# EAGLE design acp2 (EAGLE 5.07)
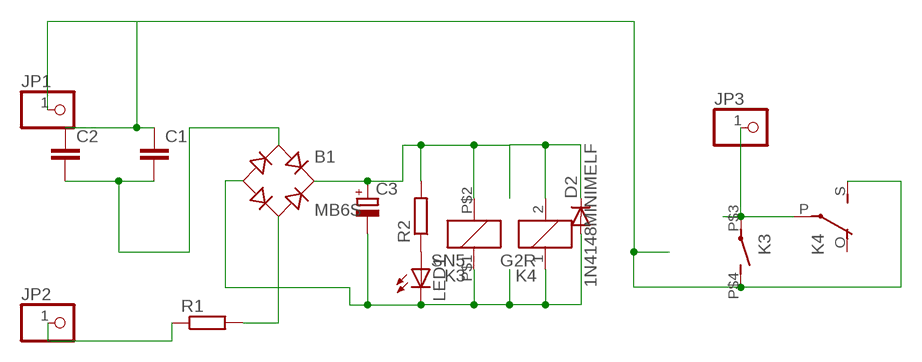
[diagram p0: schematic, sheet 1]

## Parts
B1  MB6S  [SOIC-4]
C1  C-EU150-054X183  [C150-054X183]
C2  C-EU150-054X183  [C150-054X183]
C3  CPOL-EUE2.5-5  [E2,5-5]
D2  1N4148MINIMELF  [MINIMELF]
JP1  PINHD-1X11MM6  [1X1MM8]
JP2  PINHD-1X11MM6  [1X1MM8]
JP3  PINHD-1X11MM6  [1X1MM8]
K3  SN5  [HU]
K4  G2R  [G2R]
LED1  LEDSMT1206  [1206]
R1  R-EU_0204/5  [0204/5]
R2  R-EU_R0805  [R0805]

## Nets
AC1: C1.1 C2.1 JP1.1 K3.P$4(2:S) K4.S(2:S)
AC2: JP2.1 R1.1
ACOUT: JP3.1 K3.P$3(2:P) K4.P(2:P)
MINUS: B1.- C3.- D2.A K3.P$1 K4.1 LED1.C
N$1: LED1.A R2.1
PLUS: B1.+ C3.+ D2.C K3.P$2 K4.2 R2.2
RAC1: B1.~1(AC1) C1.2 C2.2
RAC2: B1.~2(AC2) R1.2
Unconnected: K4.O(2:O)

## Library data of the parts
B1 = rectifier:MB*S: Bridge Rectifier Source: http://www.fairchildsemi.com/ds/MB/MB6S.pdf
C1 C2 = rcl:C-EU: CAPACITOR, European symbol
C3 = rcl:CPOL-EU: POLARIZED CAPACITOR, European symbol
D2 = diode-1:1N4148: DIODE
JP1-JP3 = pinhead:PINHD-1X1: PIN HEADER
K3 = relay:SN*: Slim PCB Relay 1 pole 6 A SCHRACK Source: http://www.schrack.com/.. 5815.pdf
K4 = relay:G2R: RELAY 1 x switch, Omron
LED1 = led:LED: LED
R1 R2 = rcl:R-EU_: RESISTOR, European symbol

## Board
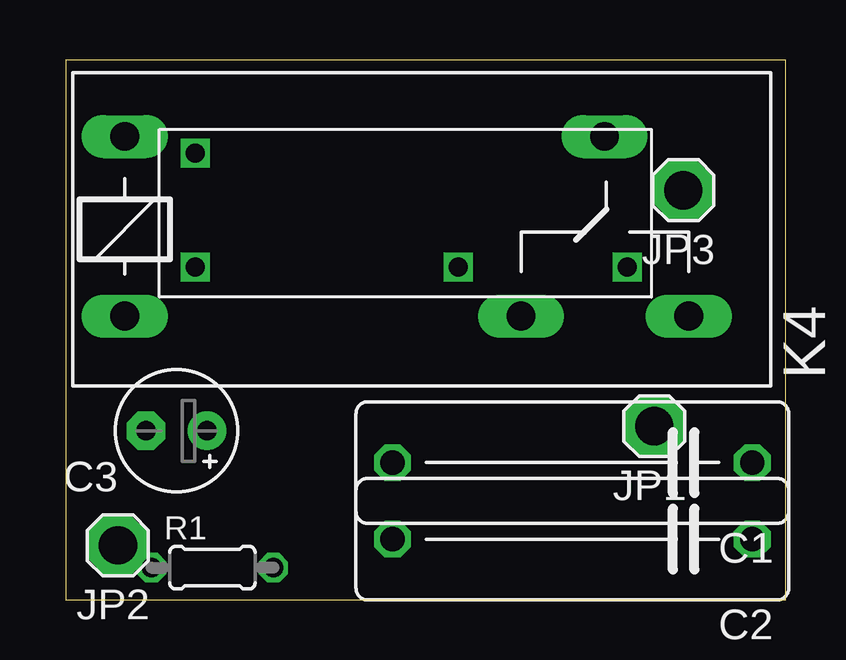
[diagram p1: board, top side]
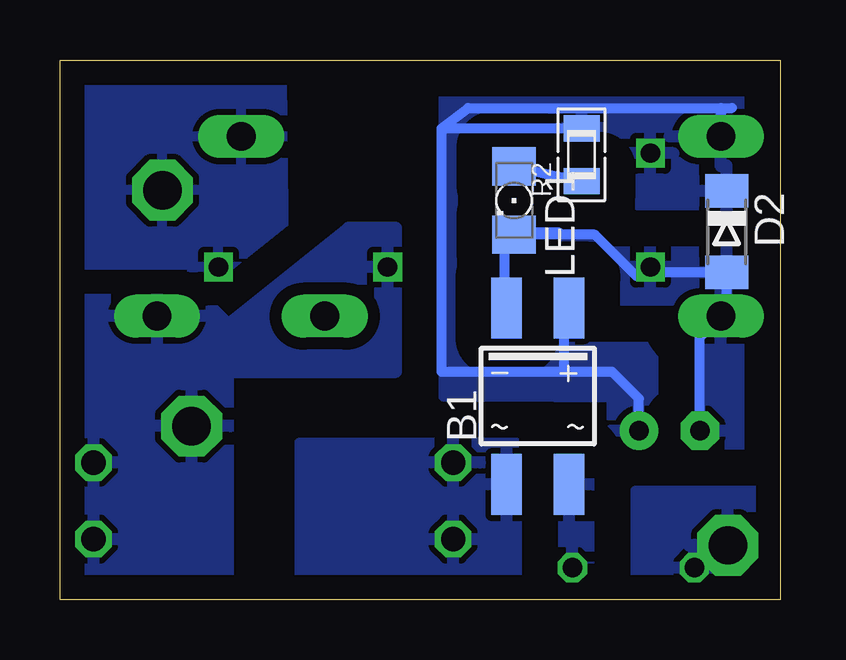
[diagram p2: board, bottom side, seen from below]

Size 30 x 22.5 mm. Coordinates in mm from the lower left corner, seen from the top.
Outline: 30,22.5 0,22.5 0,0 30,0 30,22.5
Copper layers (1*16): Top 0.035mm / dielectric 1.5mm / Bottom 0.035mm
Design rules "default *": minimum track width 10mil, minimum drill 20mil, track to track 8mil, track to pad 8mil, pad to pad 8mil, via to via 8mil, smd to smd 8mil, copper to edge 40mil, drill to drill 8mil, minimum pad ring 1mil, minimum via ring 8mil, stop-mask expansion 4mil, vias tented up to drill 0mil, thermal gap 10mil

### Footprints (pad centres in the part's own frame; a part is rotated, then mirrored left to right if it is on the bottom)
SOIC-4 = smd 1.27 x 2.54: + 1.3,3.685; - -1.3,3.685; ~1 -1.3,-3.685; ~2 1.3,-3.685
C150-054X183 = drill 1.016 octagon: 1 -7.493,0; 2 7.493,0
E2,5-5 = drill 0.813 pad 1.6 round: + -1.27,0 | drill 0.813 pad 1.6 octagon: - 1.27,0
MINIMELF = smd 1.4 x 1.8: A 1.7,0; C -1.7,0
1X1MM8 = drill 1.6 pad 2.54 octagon: 1 0,0
HU = drill 0.8 square: P$1 2.25,-9; P$2 -2.5,-9; P$3 2.25,9; P$4 2.25,1.95
G2R = drill 1.2 pad 1.778 long: 1 -2.54,-3.683; 2 -2.54,3.81; O 13.97,-3.683; P 17.45,3.81; S 20.955,-3.683
1206 = smd 1.6 x 1.803: A -1.422,0; C 1.422,0
0204/5 = drill 0.813 octagon: 1 -2.54,0; 2 2.54,0
R0805 = smd 1.1 x 1.5: 1 -1.1,0; 2 1.1,0

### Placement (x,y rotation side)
B1  10.09,8.48 0 bottom
C1  21.11,5.71 180 top
C2  21.11,2.52 180 top
C3  4.61,7.04 180 top
D2  2.22,15.34 270 bottom
JP1  24.52,7.23 180 top
JP2  2.17,2.26 180 top
JP3  25.73,17.07 180 top
K3  14.4,16.11 270 top
K4  5,15.5 0 top
LED1  11.08,16.64 270 bottom
R1  6.11,1.33 0 top
R2  8.27,18.55 90 bottom

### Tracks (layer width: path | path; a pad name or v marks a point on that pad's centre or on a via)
AC1
  pour Bottom (isolate 0.5): 16,9.5 16,15.5 18,15.5 23,11.5 23,9.5
  pour Bottom (isolate 1): 29,12.5 29,0.5 23,0.5 23,9.5 23,11.5 24,12.5
AC2
  pour Bottom (isolate 1): 0,4.5 6,4.5 6,-0.5 0,-0.5 0,3.5
ACOUT
  pour Bottom (isolate 1, rank 2): 28.93,13.5 22.79,13.4 20.65,14.34 20.75,21.75 29,21.75
MINUS
  Bottom 0.406: B1.- 11.5,12.16 11.5,15.3 9.18,15.3 LED1.C 7.72,15.22 6,13.5 5.76,13.5 K3.P$1 5.18,13.64 D2.A 2.22,12.06 K4.1 3.34,10.94 C3.-
  pour Bottom (isolate 1.5, rank 3): 4,6.5 1,6.5 1,15.5 9,15.5 9,12.5 5,12.5 5,6.5
N$1
  Bottom 0.406: LED1.A 9.43,17.66 R2.1
PLUS
  Bottom 0.406: B1.+ 9,12.16 9,9.5 | 9,9.5 14.1,9.5 14.1,19.65 | 14.1,19.65 13,20.5 2.46,20.5 | 2.46,20.5 2,20.5 | 2.46,20.5 K4.2 | 14.1,19.65 R2.2 | C3.+ 5.88,8.38 7,9.5 9,9.5
  pour Bottom (isolate 1.5, rank 2): 1,21.5 14,21.5 14,8.5 7,8.5 7,6.5 5,6.5 5,10.5 11,10.5 11,11.5 11,18.5 6,18.5 6,16.5 1,16.5
RAC1
  pour Bottom (isolate 1): 11,6.5 20,6.5 20,0.5 11,0.5
RAC2
  pour Bottom (isolate 1.5, rank 3): 7,5.5 10,5.5 10,4.5 10,0.5 7,0.5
